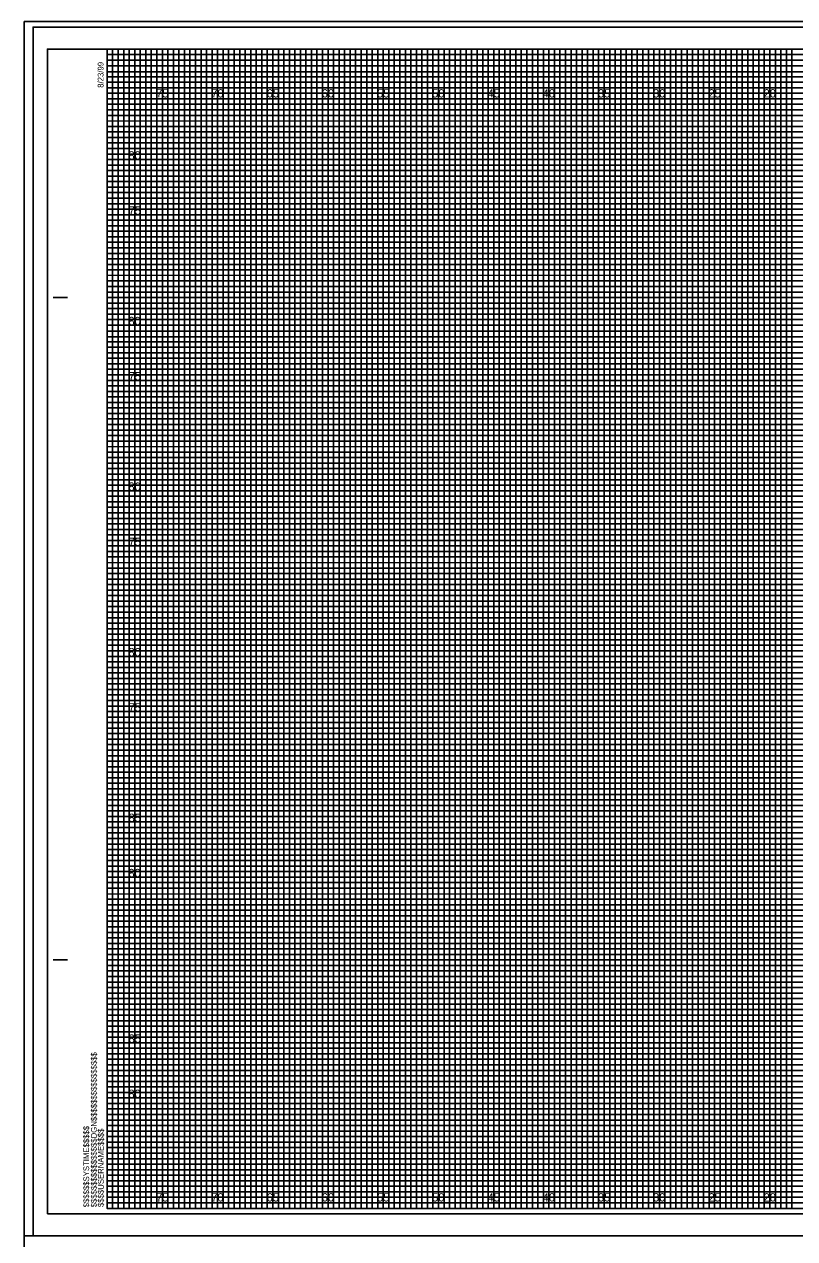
# Model space of a CAD drawing. Extents: x -8 to 533, y -20 to 768.
# Drawn here: x -7.5 to 62.2, y 107.2 to 217.2 of the extents above; entities that cross this region are included whole.
import ezdxf

# ---------------------------------------------------------------- set-up
doc = ezdxf.new("R2010")
doc.units = 0
for name, color, linetype in [('Prop XS Elevation Labels', 7, 'Continuous'), ('Prop XS Offset Labels', 7, 'Continuous'), ('Sheet Cross Section CELL', 7, 'Continuous'), ('Sheet Cross Section Grid Major CELL', 7, 'Continuous'), ('Sheet Cross Section Grid Middle CELL', 7, 'Continuous'), ('Sheet Cross Section Grid Minor 1 CELL', 7, 'Continuous'), ('Sheet Cross Section Grid Minor 2 CELL', 7, 'Continuous'), ('Sheet Cutting Line CELL', 7, 'Continuous'), ('Sheet DOT Grid CELL', 7, 'Continuous'), ('Sheet Plot Border Inside CELL', 7, 'Continuous'), ('Sheet Plot Border Outside CELL', 7, 'Continuous'), ('WEI Plot Border', 7, 'Continuous')]:
    doc.layers.add(name, color=color, linetype=linetype)

msp = doc.modelspace()

# ---------------------------------------------------------------- linework, layer by layer
at = {"layer": 'Sheet Cross Section CELL'}
for p, q in [((-4.9, 192.5), (-3.65, 192.5)), ((-4.85, 192.5), (-3.6, 192.5)), ((-4.9, 132.5), (-3.65, 132.5)), ((-4.85, 132.5), (-3.6, 132.5)), ((0, 110), (0, 110)), ((0, 110), (0, 110)), ((0, 110), (0, 110)), ((0, 110), (0, 110)), ((0, 110), (0, 110)), ((0, 110), (0, 110)), ((0, 110), (0, 110))]:
    msp.add_line(p, q, dxfattribs=at)
msp.add_lwpolyline([(160, 215), (0, 215), (0, 110), (160, 110)], close=True, dxfattribs=at)
at = {"layer": 'Sheet Cross Section Grid Major CELL'}
for p, q in [((5, 215), (0, 215)), ((5, 110), (5, 215)), ((15, 215), (10, 215)), ((10, 215), (10, 110)), ((15, 110), (15, 215)), ((25, 215), (20, 215)), ((20, 215), (20, 110)), ((25, 110), (25, 215)), ((35, 215), (30, 215)), ((30, 215), (30, 110)), ((35, 110), (35, 215)), ((45, 215), (40, 215)), ((40, 215), (40, 110)), ((45, 110), (45, 215)), ((55, 215), (50, 215)), ((50, 215), (50, 110)), ((55, 110), (55, 215)), ((65, 215), (60, 215)), ((60, 215), (60, 110)), ((10, 110), (5, 110)), ((20, 110), (15, 110)), ((30, 110), (25, 110)), ((40, 110), (35, 110)), ((50, 110), (45, 110)), ((60, 110), (55, 110))]:
    msp.add_line(p, q, dxfattribs=at)
for points in [[(0, 210), (160, 210), (160, 205), (0, 205)], [(0, 200), (160, 200), (160, 195), (0, 195)], [(0, 190), (160, 190), (160, 185), (0, 185)], [(0, 180), (160, 180), (160, 175), (0, 175)], [(0, 170), (160, 170), (160, 165), (0, 165)], [(0, 160), (160, 160), (160, 155), (0, 155)], [(0, 150), (160, 150), (160, 145), (0, 145)], [(0, 140), (160, 140), (160, 135), (0, 135)], [(0, 130), (160, 130), (160, 125), (0, 125)], [(0, 120), (160, 120), (160, 115), (0, 115)]]:
    msp.add_lwpolyline(points, dxfattribs=at)
at = {"layer": 'Sheet Cross Section Grid Middle CELL'}
for points in [[(0, 215), (2.5, 215), (2.5, 110), (7.5, 110), (7.5, 215), (12.5, 215), (12.5, 110), (17.5, 110), (17.5, 215), (22.5, 215), (22.5, 110), (27.5, 110), (27.5, 215), (32.5, 215), (32.5, 110), (37.5, 110), (37.5, 215), (42.5, 215), (42.5, 110), (47.5, 110), (47.5, 215), (52.5, 215), (52.5, 110), (57.5, 110), (57.5, 215), (62.5, 215)], [(0, 212.5), (137.5, 212.5)], [(0, 202.5), (160, 202.5), (160, 207.5), (0, 207.5)], [(0, 192.5), (160, 192.5), (160, 197.5), (0, 197.5)], [(0, 182.5), (160, 182.5), (160, 187.5), (0, 187.5)], [(0, 172.5), (160, 172.5), (160, 177.5), (0, 177.5)], [(0, 162.5), (160, 162.5), (160, 167.5), (0, 167.5)], [(0, 152.5), (160, 152.5), (160, 157.5), (0, 157.5)], [(0, 142.5), (160, 142.5), (160, 147.5), (0, 147.5)], [(0, 132.5), (160, 132.5), (160, 137.5), (0, 137.5)], [(0, 122.5), (160, 122.5), (160, 127.5), (0, 127.5)], [(0, 112.5), (160, 112.5), (160, 117.5), (0, 117.5)]]:
    msp.add_lwpolyline(points, dxfattribs=at)
at = {"layer": 'Sheet Cross Section Grid Minor 1 CELL'}
for p, q in [((0, 214.5), (130, 214.5)), ((130, 213.99), (0, 213.99)), ((0, 213.99), (0, 213.5)), ((0, 213.5), (130, 213.5)), ((130, 212.94), (0, 212.94)), ((0, 212.94), (0, 212)), ((0, 212), (160, 212))]:
    msp.add_line(p, q, dxfattribs=at)
for points in [[(0, 211.5), (135, 211.5), (160, 211.5), (160, 211), (0, 211)], [(0, 210.5), (160, 210.5), (160, 209.5), (0, 209.5)], [(0, 209), (160, 209), (160, 208.5), (0, 208.49)], [(0, 208), (160, 208), (160, 207), (0, 207)], [(0, 206.5), (160, 206.5), (160, 206), (0, 206)], [(0, 205.5), (160, 205.5), (160, 204.5), (0, 204.5)], [(0, 204), (160, 204), (160, 203.5), (0, 203.5)], [(0, 203), (160, 203), (160, 202), (0, 202)], [(0, 201.5), (160, 201.5), (160, 201), (0, 201)], [(0, 200.5), (160, 200.5), (160, 199.5), (0, 199.5)], [(0, 199), (160, 199), (160, 198.5), (0, 198.5)], [(0, 198), (160, 198), (160, 196.97), (160, 196.5), (160, 196), (0, 196)], [(0, 197), (160, 197), (160, 196.5), (0, 196.5)], [(0, 195.5), (160, 195.5), (160, 194.5), (0, 194.52)], [(0, 194.52), (160, 194.5), (160, 194), (0, 194)], [(0, 193.5), (160, 193.5), (160, 193), (0, 193)], [(0, 192), (160, 192), (160, 191.5), (0, 191.5)], [(0, 191), (160, 191), (160, 190.5), (0, 190.5)], [(-0.04, 189.44), (160, 189.44), (160, 188.94), (-0.04, 188.94)], [(0, 188.5), (160, 188.5), (160, 188), (0, 188)], [(0, 187), (160, 187), (160, 186.5), (0, 186.5)], [(0, 186), (160, 186), (160, 185.5), (0, 185.5)], [(0, 184.5), (160, 184.5), (160, 184), (0, 184)], [(0, 183.5), (160, 183.5), (160, 183), (0, 183)], [(0, 182), (160, 182), (160, 181.5), (0, 181.5)], [(0, 181), (160, 181), (160, 180.5), (0, 180.5)], [(0, 179.5), (160, 179.5), (160, 178.99), (0, 179)], [(0, 178.5), (160, 178.5), (160, 178), (0, 178)], [(0, 177), (160, 177), (160, 176.5), (0, 176.5)], [(0, 176), (160, 176), (160, 175.5), (0, 175.5)], [(0, 174.5), (160, 174.5), (160, 174), (0, 174)], [(0, 173.5), (160, 173.5), (160, 173), (0, 173)], [(0, 172), (160, 172), (160, 171.5), (0, 171.5)], [(0, 171), (160, 171), (160, 170.5), (0, 170.5)], [(0, 169.5), (160, 169.5), (160, 169), (0, 169)], [(0, 168.5), (160.03, 168.46), (160, 168), (0, 168)], [(0, 167), (160, 167), (160, 166.5), (0, 166.5)], [(0, 166), (160, 166), (160, 165.5), (0, 165.5)], [(0, 164.5), (160, 164.5), (160, 164), (0, 164)], [(0, 163.5), (160, 163.5), (160, 163), (0, 163)], [(0, 162), (160, 162), (160, 161.5), (0, 161.5)], [(0, 161), (160, 161), (160, 160.5), (0, 160.5)], [(0, 159.5), (160, 159.5), (160, 159), (0, 159)], [(0, 158.5), (160, 158.5), (160, 158), (0, 158)], [(0, 157), (160, 157), (160, 156.5), (0, 156.5)], [(0, 156), (160, 156), (160, 155.5), (0, 155.5)], [(0, 154.5), (160, 154.5), (160, 154), (0, 154)], [(0, 153.5), (160, 153.5), (160, 153), (0, 153)], [(0, 152), (160, 152), (160, 151.5), (0, 151.5)], [(0, 151), (160, 151), (160, 150.5), (0, 150.5)], [(0, 149.5), (160, 149.5), (160, 148.99), (0, 149)], [(0, 148.5), (160, 148.5), (160, 148), (0, 148)], [(0, 147), (160, 147), (160, 146.5), (0, 146.5)], [(0, 146), (160, 146), (160, 145.5), (0, 145.5)], [(0, 144.5), (160, 144.5), (160, 144), (0, 144)], [(0, 143.5), (160, 143.5), (160, 143), (0, 143)], [(0, 142), (160, 142), (160, 141.5), (0, 141.5)], [(0, 141), (160, 141), (160, 140.5), (0, 140.5)], [(0, 139.5), (160, 139.5), (160, 139), (0, 139)], [(0, 138.5), (160.03, 138.46), (160, 138), (0, 138)], [(0, 137), (160, 137), (160, 136.5), (0, 136.5)], [(0, 136), (160, 136), (160, 135.5), (0, 135.5)], [(0, 134.5), (160, 134.5), (160, 134), (0, 134)], [(0, 133.5), (160, 133.5), (160, 133), (0, 133)], [(0, 132), (160, 132), (160, 131.5), (0, 131.5)], [(0, 131), (160, 131), (160, 130.5), (0, 130.5)], [(0, 129.5), (160, 129.5), (160, 129), (0, 129)], [(0, 128.5), (160, 128.5), (160, 128), (0, 128)], [(0, 127), (160, 127), (160, 126.5), (0, 126.5)], [(0, 126), (160, 126), (160, 125.5), (0, 125.5)], [(0, 124.5), (160, 124.5), (160, 124), (0, 124)], [(0, 123.5), (160, 123.5), (160, 123), (0, 123)], [(0, 122), (160, 122), (160, 121.5), (0, 121.5)], [(0, 121), (160, 121), (160, 120.5), (0, 120.5)], [(0, 119.5), (160, 119.5), (160, 119), (0, 119)], [(0, 118.5), (160, 118.5), (160, 118), (0, 118)], [(0, 117), (160, 117), (160, 116.5), (0, 116.5)], [(0, 116), (160, 116), (160, 115.5), (0, 115.5)], [(0, 114.5), (160, 114.5), (160, 114), (0, 114)], [(0, 113.5), (160, 113.5), (160, 113), (0, 113)], [(0, 112), (160, 112), (160, 111.5), (0, 111.5)], [(0, 111), (160, 111), (160, 110.5), (0, 110.5)]]:
    msp.add_lwpolyline(points, dxfattribs=at)
at = {"layer": 'Sheet Cross Section Grid Minor 2 CELL'}
for points in [[(0, 110), (0.5, 110), (0.5, 215), (1, 215), (1, 110)], [(1, 110), (1.5, 110), (1.5, 215), (2, 215), (2, 110)], [(2.5, 110), (3, 110), (3, 215), (3.5, 215), (3.5, 110)], [(3.5, 110), (4, 110), (4, 215), (4.5, 215), (4.5, 110)], [(5, 110), (5.5, 110), (5.5, 215), (6, 215), (6, 110)], [(6, 110), (6.5, 110), (6.5, 215), (7, 215), (7, 110)], [(7.5, 110), (8, 110), (8, 215), (8.5, 215), (8.5, 110)], [(8.5, 110), (9, 110), (9, 215), (9.5, 215), (9.5, 110)], [(10, 110), (10.5, 110), (10.5, 215), (11, 215), (11, 110)], [(11, 110), (11.5, 110), (11.5, 215), (12, 215), (12, 110)], [(12.5, 110), (13, 110), (13, 215), (13.5, 215), (13.5, 110)], [(13.5, 110), (14, 110), (14, 215), (14.5, 215), (14.5, 110)], [(15, 110), (15.5, 110), (15.5, 215), (16, 215), (16, 110)], [(16, 110), (16.5, 110), (16.5, 215), (17, 215), (17, 110)], [(17.5, 110), (18, 110), (18, 215), (18.5, 215), (18.5, 110)], [(18.5, 110), (19, 110), (19, 215), (19.5, 215), (19.5, 110)], [(20, 110), (20.5, 110), (20.5, 215), (21, 215), (21, 110)], [(21, 110), (21.5, 110), (21.5, 215), (22, 215), (22, 110)], [(22.5, 110), (23, 110), (23, 215), (23.5, 215), (23.5, 110)], [(23.5, 110), (24, 110), (24, 215), (24.5, 215), (24.5, 110)], [(25, 110), (25.5, 110), (25.5, 215), (26, 215), (26, 110)], [(26, 110), (26.5, 110), (26.5, 215), (27, 215), (27, 110)], [(27.5, 110), (28, 110), (28, 215), (28.5, 215), (28.5, 110)], [(28.5, 110), (29, 110), (29, 215), (29.5, 215), (29.5, 110)], [(30, 110), (30.5, 110), (30.5, 215), (31, 215), (31, 110)], [(31, 110), (31.5, 110), (31.5, 215), (32, 215), (32, 110)], [(32.5, 110), (33, 110), (33, 215), (33.5, 215), (33.5, 110)], [(33.5, 110), (34, 110), (34, 215), (34.5, 215), (34.5, 110)], [(35, 110), (35.5, 110), (35.5, 215), (36, 215), (36, 110)], [(36, 110), (36.5, 110), (36.5, 215), (37, 215), (37, 110)], [(37.5, 110), (38, 110), (38, 215), (38.5, 215), (38.5, 110)], [(38.5, 110), (39, 110), (39, 215), (39.5, 215), (39.5, 110)], [(40, 110), (40.5, 110), (40.5, 215), (41, 215), (41, 110)], [(41, 110), (41.5, 110), (41.5, 215), (42, 215), (42, 110)], [(42.5, 110), (43, 110), (43, 215), (43.5, 215), (43.5, 110)], [(43.5, 110), (44, 110), (44, 215), (44.5, 215), (44.5, 110)], [(45, 110), (45.5, 110), (45.5, 215), (46, 215), (46, 110)], [(46, 110), (46.5, 110), (46.5, 215), (47, 215), (47, 110)], [(47.5, 110), (48, 110), (48, 215), (48.5, 215), (48.5, 110)], [(48.5, 110), (49, 110), (49, 215), (49.5, 215), (49.5, 110)], [(50, 110), (50.5, 110), (50.5, 215), (51, 215), (51, 110)], [(51, 110), (51.5, 110), (51.5, 215), (52, 215), (52, 110)], [(52.5, 110), (53, 110), (53, 215), (53.5, 215), (53.5, 110)], [(53.5, 110), (54, 110), (54, 215), (54.5, 215), (54.5, 110)], [(55, 110), (55.5, 110), (55.5, 215), (56, 215), (56, 110)], [(56, 110), (56.5, 110), (56.5, 215), (57, 215), (57, 110)], [(57.5, 110), (58, 110), (58, 215), (58.5, 215), (58.5, 110)], [(58.5, 110), (59, 110), (59, 215), (59.5, 215), (59.5, 110)], [(60, 110), (60.5, 110), (60.5, 215), (61, 215), (61, 110)], [(61, 110), (61.5, 110), (61.5, 215), (62, 215), (62, 110)]]:
    msp.add_lwpolyline(points, dxfattribs=at)
at = {"layer": 'Sheet Cutting Line CELL'}
for p, q in [((161.65, 217), (-6.7, 217)), ((-6.7, 217), (-6.7, 107.5)), ((-6.7, 107.5), (161.65, 107.5))]:
    msp.add_line(p, q, dxfattribs=at)
at = {"layer": 'Sheet DOT Grid CELL'}
for p, q in [((5, 110), (5, 215)), ((10, 110), (10, 215)), ((15, 110), (15, 215)), ((20, 110), (20, 215)), ((25, 110), (25, 215)), ((30, 110), (30, 215)), ((35, 110), (35, 215)), ((40, 110), (40, 215)), ((45, 110), (45, 215)), ((50, 110), (50, 215)), ((55, 110), (55, 215)), ((60, 110), (60, 215)), ((0, 210), (160, 210)), ((0, 205), (160, 205)), ((0, 200), (160, 200)), ((0, 195), (160, 195)), ((0, 190), (160, 190)), ((0, 185), (160, 185)), ((0, 180), (160, 180)), ((0, 175), (160, 175)), ((0, 170), (160, 170)), ((0, 165), (160, 165)), ((0, 160), (160, 160)), ((0, 155), (160, 155)), ((0, 150), (160, 150)), ((0, 145), (160, 145)), ((0, 140), (160, 140)), ((0, 135), (160, 135)), ((0, 130), (160, 130)), ((0, 125), (160, 125)), ((0, 120), (160, 120)), ((0, 115), (160, 115))]:
    msp.add_line(p, q, dxfattribs=at)
at = {"layer": 'Sheet Plot Border Inside CELL'}
msp.add_lwpolyline([(-5.4, 109.5), (161.2, 109.5), (161.2, 215), (-5.4, 215)], close=True, dxfattribs=at)
at = {"layer": 'Sheet Plot Border Outside CELL'}
msp.add_lwpolyline([(-6.7, 107.5), (161.65, 107.5), (161.65, 217), (-6.7, 217)], close=True, dxfattribs=at)
at = {"layer": 'WEI Plot Border'}
for points in [[(-7.5, 107.5), (162.5, 107.5), (162.5, 217.5), (-7.5, 217.5)], [(-7.5, -2.5), (162.5, -2.5), (162.5, 107.5), (-7.5, 107.5)]]:
    msp.add_lwpolyline(points, close=True, dxfattribs=at)

# ---------------------------------------------------------------- texts
at = {"layer": 'Prop XS Elevation Labels'}
for s, p in [('80', (1.93, 205)), ('75', (1.94, 200)), ('80', (1.93, 190)), ('75', (1.94, 185)), ('80', (1.93, 175)), ('75', (1.94, 170)), ('80', (1.93, 160)), ('75', (1.94, 155)), ('85', (1.94, 145)), ('80', (1.93, 140)), ('85', (1.94, 125)), ('80', (1.93, 120))]:
    msp.add_text(s, height=0.75, dxfattribs=at).set_placement(p)
at = {"layer": 'Prop XS Offset Labels'}
for s, p in [('75', (4.44, 210.62)), ('70', (9.43, 210.62)), ('65', (14.44, 210.62)), ('60', (19.43, 210.62)), ('55', (24.44, 210.62)), ('50', (29.43, 210.62)), ('45', (34.44, 210.62)), ('40', (39.43, 210.62)), ('35', (44.44, 210.62)), ('30', (49.43, 210.62)), ('25', (54.44, 210.62)), ('20', (59.43, 210.62)), ('75', (4.44, 110.62)), ('70', (9.43, 110.62)), ('65', (14.44, 110.62)), ('60', (19.43, 110.62)), ('55', (24.44, 110.62)), ('50', (29.43, 110.62)), ('45', (34.44, 110.62)), ('40', (39.43, 110.62)), ('35', (44.44, 110.62)), ('30', (49.43, 110.62)), ('25', (54.44, 110.62)), ('20', (59.43, 110.62))]:
    msp.add_text(s, height=0.75, dxfattribs=at).set_placement(p)
at = {"layer": 'Sheet Cross Section CELL'}
for s, p in [('8/23/99', (-0.33, 211.5)), ('$$$$$$$$$$$$$$$$DGN$$$$$$$$$$$$$$$$', (-0.94, 110.09)), ('$$$$$$SYSTIME$$$$$', (-1.63, 110.09)), ('$$$$USERNAME$$$$', (-0.31, 110.12))]:
    msp.add_text(s, height=0.525, rotation=90, dxfattribs=at).set_placement(p)

doc.saveas('drawing.dxf')
